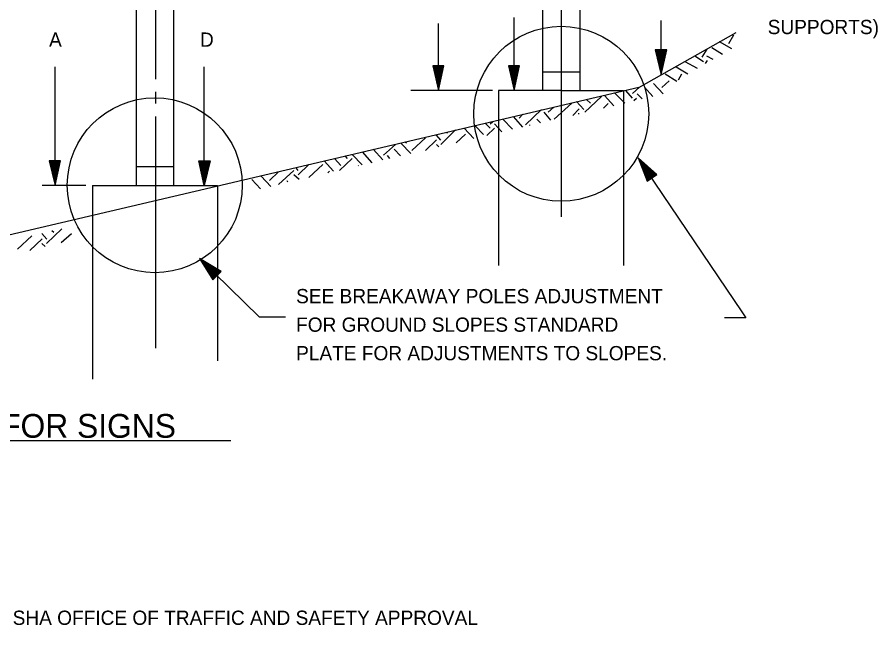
# Model space of a CAD drawing. Extents: x 139.2 to 146.5, y 202.4 to 212.6.
# Drawn here: x 142.714 to 146.334, y 207.545 to 210.118 of the extents above; entities that cross this region are included whole.
import ezdxf

# ---------------------------------------------------------------- set-up
doc = ezdxf.new("R2010")
doc.units = 0
for name, color, linetype in [('DETL-DIMS', 7, 'Continuous'), ('DETL-LINE', 7, 'Continuous'), ('DETL-NOTE', 7, 'Continuous'), ('MSHA-LOGO', 7, 'Continuous'), ('TTLB-TEXT', 7, 'Continuous')]:
    doc.layers.add(name, color=color, linetype=linetype)

msp = doc.modelspace()

# ---------------------------------------------------------------- linework, layer by layer
at = {"layer": 'DETL-DIMS'}
for p, q in [((143.295, 211.152), (143.295, 209.857)), ((145.002, 210.173), (145.002, 209.805)), ((144.8049, 209.81), (144.8049, 210.1166)), ((145.422, 209.8759), (145.422, 210.105)), ((144.4864, 209.81), (144.4864, 210.0924)), ((142.873, 209.41), (142.873, 209.91)), ((143.5008, 209.41), (143.5008, 209.91)), ((144.713, 209.81), (144.3698, 209.81)), ((143.295, 209.805), (143.295, 209.755)), ((145.002, 209.805), (145.002, 209.278)), ((143.295, 209.701), (143.295, 208.726)), ((143.003, 209.41), (142.819, 209.41)), ((143.3708, 209.41), (143.5548, 209.41)), ((143.4804, 209.1029), (143.7314, 208.8579)), ((143.7314, 208.8579), (143.8424, 208.8579))]:
    msp.add_line(p, q, dxfattribs=at)
for points in [[(145.398, 209.9809), (145.422, 209.8759), (145.446, 209.9809), (145.398, 209.9809)], [(145.401, 209.9789), (145.422, 209.8879), (145.441, 209.9789), (145.401, 209.9789)], [(145.402, 209.9759), (145.422, 209.8979), (145.44, 209.9759), (145.402, 209.9759)], [(145.406, 209.9729), (145.422, 209.9089), (145.436, 209.9729), (145.406, 209.9729)], [(145.408, 209.9719), (145.422, 209.9169), (145.432, 209.9719), (145.408, 209.9719)], [(145.411, 209.9689), (145.422, 209.9269), (145.431, 209.9689), (145.411, 209.9689)], [(145.415, 209.9679), (145.422, 209.9369), (145.43, 209.9679), (145.415, 209.9679)], [(145.416, 209.9639), (145.422, 209.9469), (145.426, 209.9639), (145.416, 209.9639)], [(145.421, 209.9629), (145.422, 209.9569), (145.422, 209.9629), (145.421, 209.9629)], [(144.4624, 209.914), (144.4864, 209.81), (144.5084, 209.914), (144.4624, 209.914)], [(144.4644, 209.913), (144.4864, 209.821), (144.5074, 209.913), (144.4644, 209.913)], [(144.4684, 209.909), (144.4864, 209.831), (144.5034, 209.909), (144.4684, 209.909)], [(144.4694, 209.908), (144.4864, 209.842), (144.4994, 209.908), (144.4694, 209.908)], [(144.4734, 209.906), (144.4864, 209.851), (144.4984, 209.906), (144.4734, 209.906)], [(144.4744, 209.904), (144.4864, 209.862), (144.4964, 209.904), (144.4744, 209.904)], [(144.4784, 209.903), (144.4864, 209.871), (144.4934, 209.903), (144.4784, 209.903)], [(144.4834, 209.898), (144.4864, 209.881), (144.4894, 209.898), (144.4834, 209.898)], [(144.4834, 209.897), (144.4864, 209.892), (144.4874, 209.897), (144.4834, 209.897)], [(144.7809, 209.914), (144.8049, 209.81), (144.8269, 209.914), (144.7809, 209.914)], [(144.7829, 209.913), (144.8049, 209.821), (144.8259, 209.913), (144.7829, 209.913)], [(144.7869, 209.909), (144.8049, 209.831), (144.8219, 209.909), (144.7869, 209.909)], [(144.7879, 209.908), (144.8049, 209.842), (144.8179, 209.908), (144.7879, 209.908)], [(144.7919, 209.906), (144.8049, 209.851), (144.8169, 209.906), (144.7919, 209.906)], [(144.7929, 209.904), (144.8049, 209.862), (144.8149, 209.904), (144.7929, 209.904)], [(144.7969, 209.903), (144.8049, 209.871), (144.8119, 209.903), (144.7969, 209.903)], [(144.8019, 209.898), (144.8049, 209.881), (144.8079, 209.898), (144.8019, 209.898)], [(144.8019, 209.897), (144.8049, 209.892), (144.8059, 209.897), (144.8019, 209.897)], [(145.405, 209.456), (145.326, 209.526), (145.364, 209.429), (145.405, 209.456)], [(145.329, 209.52), (145.762, 208.879), (145.779, 208.853), (145.6884, 208.8532)], [(145.402, 209.456), (145.333, 209.519), (145.365, 209.433), (145.402, 209.456)], [(142.848, 209.514), (142.873, 209.41), (142.896, 209.514), (142.848, 209.514)], [(142.852, 209.511), (142.873, 209.42), (142.891, 209.511), (142.852, 209.511)], [(142.853, 209.509), (142.873, 209.428), (142.89, 209.509), (142.853, 209.509)], [(142.857, 209.507), (142.873, 209.44), (142.888, 209.507), (142.857, 209.507)], [(142.858, 209.503), (142.873, 209.451), (142.883, 209.503), (142.858, 209.503)], [(142.863, 209.502), (142.873, 209.46), (142.881, 209.502), (142.863, 209.502)], [(142.865, 209.501), (142.873, 209.47), (142.88, 209.501), (142.865, 209.501)], [(142.868, 209.498), (142.873, 209.48), (142.877, 209.498), (142.868, 209.498)], [(142.87, 209.497), (142.873, 209.49), (142.873, 209.497), (142.87, 209.497)], [(143.5258, 209.514), (143.5008, 209.41), (143.4778, 209.514), (143.5258, 209.514)], [(143.5218, 209.511), (143.5008, 209.42), (143.4828, 209.511), (143.5218, 209.511)], [(143.5208, 209.509), (143.5008, 209.428), (143.4838, 209.509), (143.5208, 209.509)], [(143.5168, 209.507), (143.5008, 209.44), (143.4858, 209.507), (143.5168, 209.507)], [(143.5158, 209.503), (143.5008, 209.451), (143.4908, 209.503), (143.5158, 209.503)], [(143.5108, 209.502), (143.5008, 209.46), (143.4928, 209.502), (143.5108, 209.502)], [(143.5088, 209.501), (143.5008, 209.47), (143.4938, 209.501), (143.5088, 209.501)], [(143.5058, 209.498), (143.5008, 209.48), (143.4968, 209.498), (143.5058, 209.498)], [(143.5038, 209.497), (143.5008, 209.49), (143.5008, 209.497), (143.5038, 209.497)], [(145.398, 209.457), (145.338, 209.51), (145.369, 209.436), (145.398, 209.457)], [(145.394, 209.458), (145.343, 209.505), (145.369, 209.439), (145.394, 209.458)], [(145.39, 209.457), (145.35, 209.495), (145.371, 209.442), (145.39, 209.457)], [(145.387, 209.458), (145.354, 209.487), (145.372, 209.447), (145.387, 209.458)], [(145.383, 209.456), (145.36, 209.48), (145.373, 209.449), (145.383, 209.456)], [(145.379, 209.456), (145.366, 209.47), (145.373, 209.453), (145.379, 209.456)], [(145.377, 209.457), (145.371, 209.463), (145.373, 209.457), (145.377, 209.457)], [(143.5714, 209.0489), (143.4804, 209.1029), (143.5364, 209.0139), (143.5714, 209.0489)], [(143.5684, 209.0489), (143.4884, 209.0969), (143.5364, 209.0189), (143.5684, 209.0489)], [(143.5644, 209.0489), (143.4954, 209.0889), (143.5404, 209.0229), (143.5644, 209.0489)], [(143.5604, 209.0489), (143.5014, 209.0839), (143.5404, 209.0249), (143.5604, 209.0489)], [(143.5564, 209.0469), (143.5104, 209.0769), (143.5404, 209.0289), (143.5564, 209.0469)], [(143.5534, 209.0469), (143.5154, 209.0689), (143.5404, 209.0339), (143.5534, 209.0469)], [(143.5504, 209.0439), (143.5234, 209.0639), (143.5404, 209.0349), (143.5504, 209.0439)], [(143.5464, 209.0439), (143.5304, 209.0549), (143.5404, 209.0389), (143.5464, 209.0439)], [(143.5434, 209.0439), (143.5364, 209.0489), (143.5404, 209.0439), (143.5434, 209.0439)]]:
    msp.add_lwpolyline(points, dxfattribs=at)
at = {"layer": 'DETL-LINE'}
msp.add_line((141.026, 208.3369), (143.6126, 208.3369), dxfattribs=at)
at = {"layer": 'MSHA-LOGO'}
for p, q in [((145.7073, 210.0082), (145.7279, 210.0445)), ((145.6813, 209.962), (145.6357, 209.9893)), ((145.7194, 209.9847), (145.668, 210.0144)), ((145.6007, 209.9311), (145.5648, 209.9539)), ((145.5951, 209.9503), (145.6156, 209.9834)), ((145.6409, 209.9398), (145.6148, 209.954)), ((145.5759, 209.902), (145.5238, 209.9304)), ((145.6093, 209.9232), (145.617, 209.9359)), ((145.5349, 209.8784), (145.4853, 209.9087)), ((145.4958, 209.8555), (145.5093, 209.8803)), ((145.426, 209.822), (145.456, 209.851)), ((145.4888, 209.8477), (145.4393, 209.878)), ((145.302, 209.778), (145.274, 209.81)), ((145.302, 209.798), (145.331, 209.824)), ((145.388, 209.785), (145.352, 209.824)), ((145.431, 209.796), (145.39, 209.839)), ((145.102, 209.719), (145.172, 209.785)), ((145.125, 209.757), (145.11, 209.771)), ((145.224, 209.746), (145.185, 209.789)), ((145.27, 209.757), (145.228, 209.799)), ((145.308, 209.768), (145.319, 209.778)), ((145.343, 209.775), (145.322, 209.796)), ((144.948, 209.719), (144.971, 209.74)), ((144.973, 209.689), (145.047, 209.757)), ((145.097, 209.73), (145.066, 209.764)), ((145.18, 209.735), (145.2, 209.755)), ((144.841, 209.656), (144.802, 209.701)), ((144.825, 209.694), (144.841, 209.71)), ((144.852, 209.665), (144.92, 209.73)), ((144.958, 209.685), (144.93, 209.719)), ((145.051, 209.705), (145.078, 209.733)), ((145.077, 209.711), (145.077, 209.714)), ((144.703, 209.651), (144.682, 209.672)), ((144.703, 209.67), (144.714, 209.68)), ((144.753, 209.636), (144.722, 209.67)), ((144.797, 209.647), (144.756, 209.69)), ((144.87, 209.663), (144.87, 209.665)), ((144.915, 209.674), (144.899, 209.69)), ((144.496, 209.583), (144.558, 209.645)), ((144.526, 209.63), (144.521, 209.632)), ((144.56, 209.59), (144.6, 209.626)), ((144.635, 209.608), (144.594, 209.651)), ((144.675, 209.625), (144.64, 209.661)), ((144.69, 209.621), (144.722, 209.651)), ((144.348, 209.589), (144.353, 209.594)), ((144.374, 209.558), (144.431, 209.611)), ((144.431, 209.558), (144.477, 209.603)), ((144.496, 209.601), (144.477, 209.622)), ((144.252, 209.518), (144.211, 209.563)), ((144.255, 209.538), (144.305, 209.583)), ((144.326, 209.535), (144.3, 209.563)), ((144.37, 209.545), (144.328, 209.589)), ((144.488, 209.573), (144.477, 209.583)), ((144.075, 209.495), (144.048, 209.524)), ((144.069, 209.474), (144.123, 209.524)), ((144.103, 209.524), (144.094, 209.535)), ((144.165, 209.497), (144.123, 209.541)), ((144.207, 209.505), (144.166, 209.552)), ((144.281, 209.524), (144.271, 209.536)), ((143.896, 209.474), (143.888, 209.485)), ((143.896, 209.455), (143.941, 209.499)), ((143.941, 209.444), (144, 209.499)), ((144.045, 209.47), (144.005, 209.514)), ((144.148, 209.493), (144.149, 209.494)), ((143.781, 209.406), (143.74, 209.449)), ((143.775, 209.431), (143.813, 209.468)), ((143.813, 209.414), (143.878, 209.474)), ((143.9, 209.435), (143.878, 209.455)), ((144.02, 209.464), (144.027, 209.47)), ((143.738, 209.396), (143.701, 209.435)), ((143.853, 209.424), (143.85, 209.43)), ((142.837, 209.166), (142.902, 209.228)), ((142.715, 209.142), (142.776, 209.198)), ((142.839, 209.185), (142.817, 209.208)), ((142.868, 209.212), (142.86, 209.219)), ((142.899, 209.17), (142.942, 209.208)), ((142.767, 209.137), (142.819, 209.186)), ((142.831, 209.154), (142.817, 209.166))]:
    msp.add_line(p, q, dxfattribs=at)
at = {"layer": 'TTLB-TEXT'}
for p, q in [((143.214, 210.568), (143.214, 209.41)), ((143.371, 210.568), (143.371, 209.41)), ((144.923, 210.568), (144.923, 209.81)), ((145.081, 210.568), (145.081, 209.81)), ((145.3285, 209.8231), (145.7383, 210.0545)), ((144.923, 209.889), (145.081, 209.889)), ((145.3285, 209.8231), (141.452, 208.914)), ((145.002, 209.81), (144.739, 209.81)), ((144.739, 209.81), (144.739, 209.672)), ((145.002, 209.81), (145.264, 209.81)), ((145.264, 209.81), (145.264, 209.074)), ((144.739, 209.672), (144.739, 209.074)), ((143.214, 209.49), (143.371, 209.49)), ((143.03, 209.41), (143.556, 209.41)), ((143.03, 209.41), (143.03, 209.272)), ((143.556, 209.41), (143.556, 208.673)), ((143.65, 209.411), (143.65, 209.411)), ((143.03, 209.272), (143.03, 208.595))]:
    msp.add_line(p, q, dxfattribs=at)
for centre in [(145.0025, 209.712), (143.2925, 209.4111)]:
    msp.add_circle(centre, 0.368, dxfattribs=at)

# ---------------------------------------------------------------- texts
at = {"layer": 'DETL-LINE'}
msp.add_text('VERTICAL CLEARANCES FOR SIGNS', height=0.100002, dxfattribs=at).set_placement((141.0114, 208.3489))
at = {"layer": 'DETL-NOTE'}
for s, p in [('SUPPORTS)', (145.8707, 210.0471)), ('A', (142.848, 209.994)), ('D', (143.4827, 209.994)), ('SEE BREAKAWAY POLES ADJUSTMENT ', (143.8871, 208.9148)), ('FOR GROUND SLOPES STANDARD ', (143.8871, 208.7948)), ('PLATE FOR ADJUSTMENTS TO SLOPES.', (143.8871, 208.6748)), ('  ALL MOUNTING HEIGHTS LESS THAN 7\'-6" REQUIRE MDOT SHA OFFICE OF TRAFFIC AND SAFETY APPROVAL', (140.3506, 207.5616))]:
    msp.add_text(s, height=0.06, dxfattribs=at).set_placement(p)

doc.saveas('drawing.dxf')
